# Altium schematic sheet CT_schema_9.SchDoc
size 274 x 160 mm
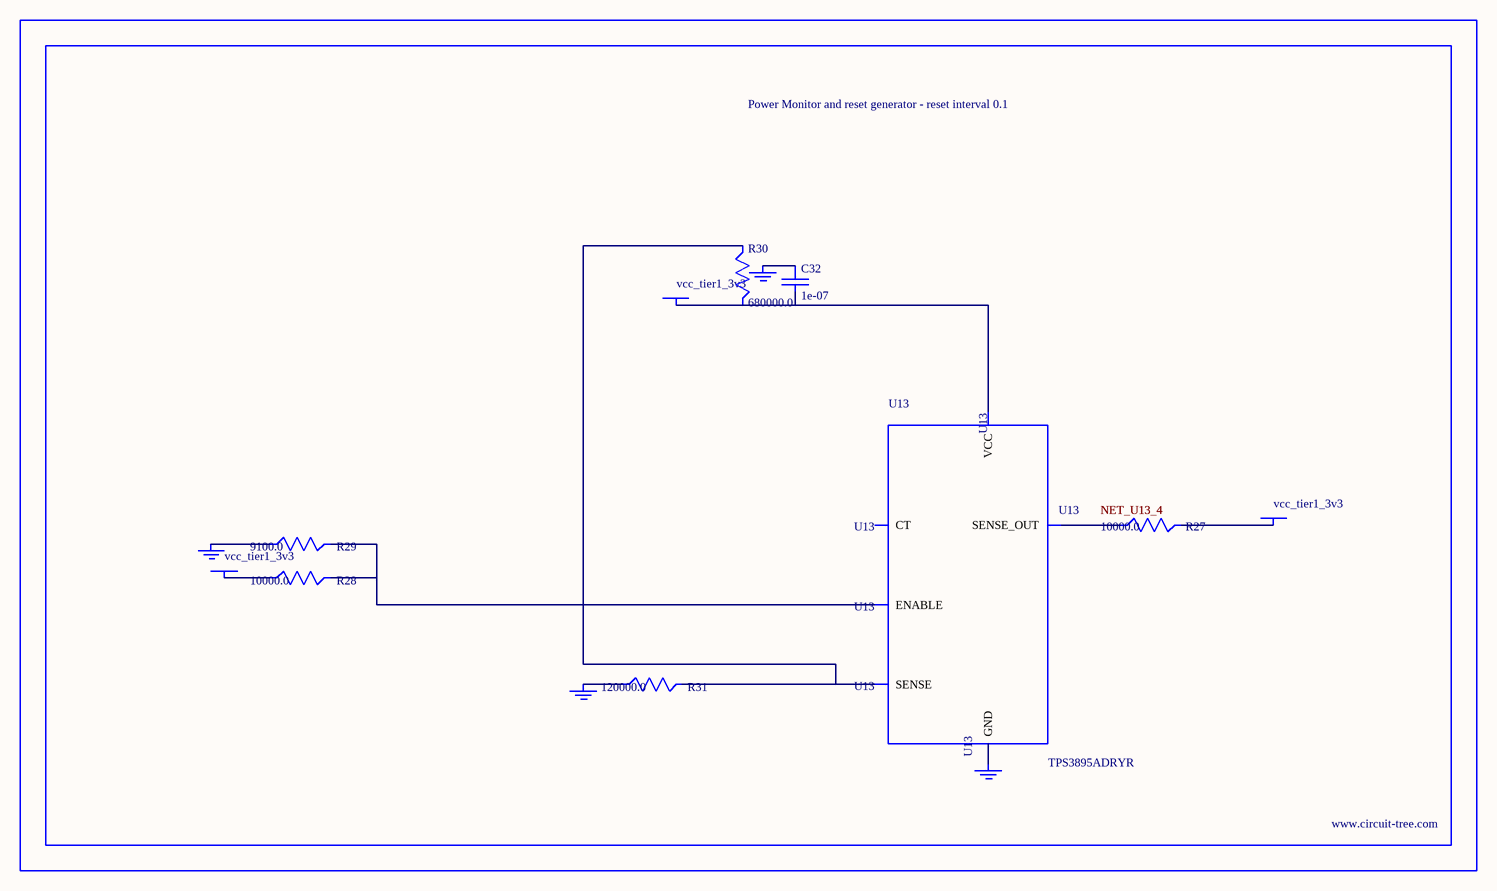
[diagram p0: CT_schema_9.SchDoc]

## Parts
BORDER8  (no value)
C32  1e-07  [C0402]
GND_INSTANCE_8_0  (no value)
GND_INSTANCE_8_1  (no value)
GND_INSTANCE_8_2  (no value)
GND_INSTANCE_8_3  (no value)
POWER_INSTANCE_8_0  vcc_tier1_3v3
POWER_INSTANCE_8_1  vcc_tier1_3v3
POWER_INSTANCE_8_2  vcc_tier1_3v3
R27  10000.0  [R0603]
R28  10000.0  [R0603]
R29  9100.0  [R0603]
R30  680000.0  [R0603]
R31  120000.0  [R0603]
U13  TPS3895ADRYR  [SON-6]

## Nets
NetC32_1: C32.1 GND_INSTANCE_8_2.0(GND)
NetC32_2: C32.2 POWER_INSTANCE_8_2.0(PWR) R30.2 U13.6(VCC)
NetGND_INSTANCE_8_0_0: GND_INSTANCE_8_0.0(GND) R29.1
NetGND_INSTANCE_8_1_0: GND_INSTANCE_8_1.0(GND) R31.1
NetGND_INSTANCE_8_3_0: GND_INSTANCE_8_3.0(GND) U13.2(GND)
NetPOWER_INSTANCE_8_0_0: POWER_INSTANCE_8_0.0(PWR) R28.1
NetPOWER_INSTANCE_8_1_0: POWER_INSTANCE_8_1.0(PWR) R27.2
NetR27_1: R27.1 U13.4(SENSE_OUT)
NetR28_2: R28.2 R29.2 U13.1(ENABLE)
NetR30_1: R30.1 R31.2 U13.3(SENSE)

Not connected (* = marked no-connect by the designer): U13 5(CT)

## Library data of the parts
BORDER8 = BORDER_PAGE8
C32 = C0402C104K3RACTU
GND_INSTANCE_8_0-GND_INSTANCE_8_3 = GND
POWER_INSTANCE_8_0-POWER_INSTANCE_8_2 = PWR
R27 R28 = RC0603JR-0710KL
R29 = RC0603JR-079K1L
R30 = RC0603JR-07680KL
R31 = RC0603JR-07120KL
